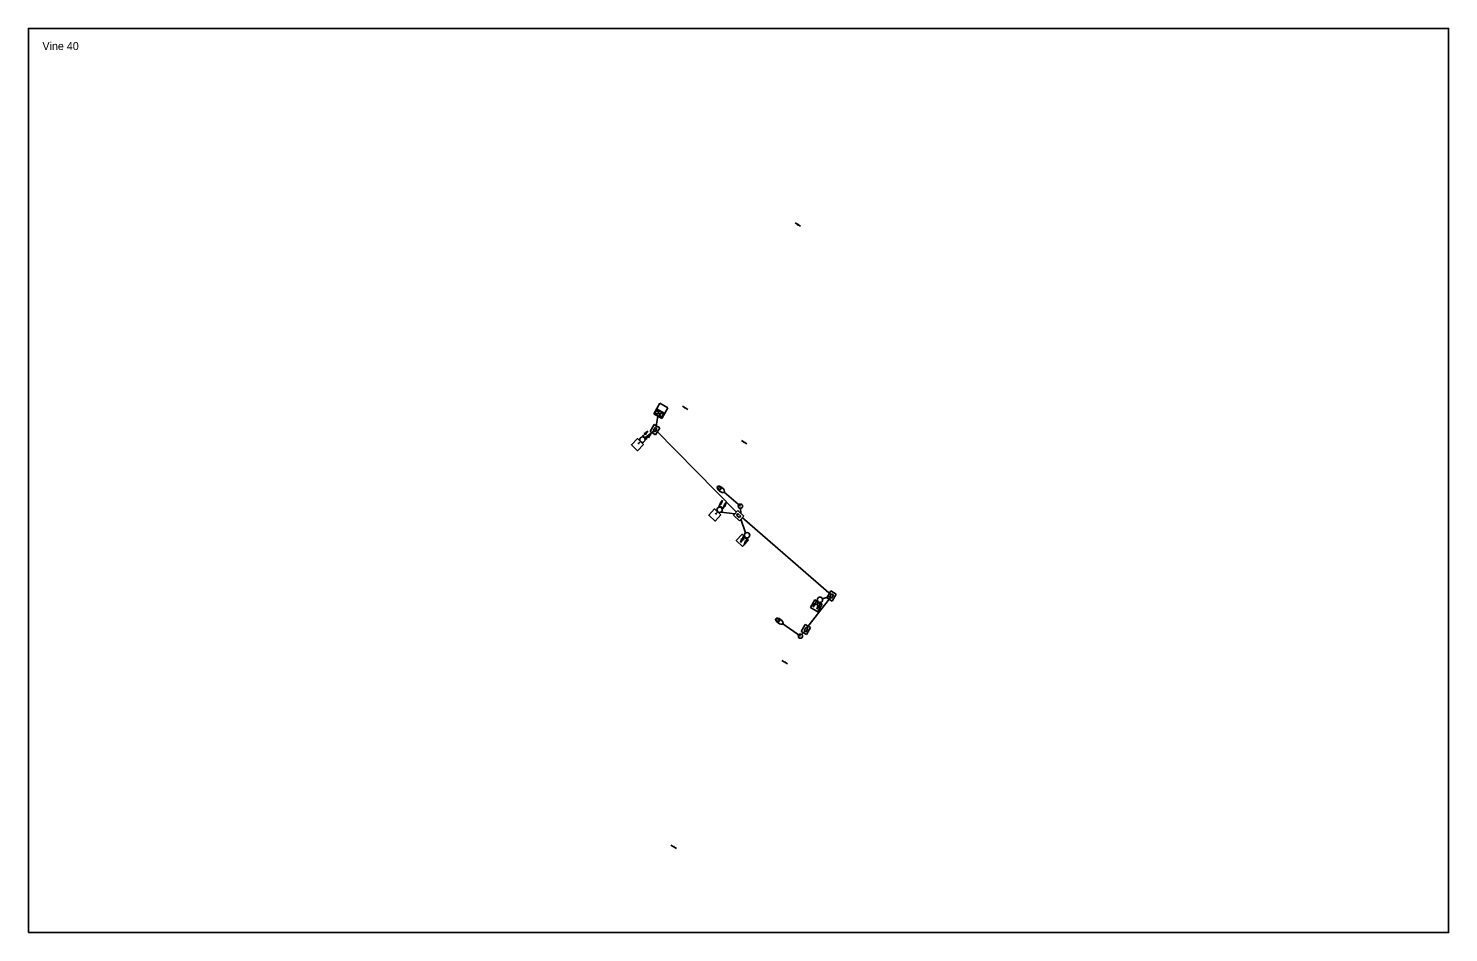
# Model space of a CAD drawing. Extents: x 995815 to 1000702, y 1981720 to 1984760.
# Drawn here: x 998107 to 998767, y 1984340 to 1984760 of the extents above; entities that cross this region are included whole.
import ezdxf

# ---------------------------------------------------------------- set-up
doc = ezdxf.new("R2010")
doc.units = 0
for name, color, linetype in [('DSN_Drain_Alignment_ArDOT_BMCD_Rt', 7, 'Continuous'), ('DSN_DRAIN_Analytics_ArDOT_BMCD_Rt', 7, 'Continuous'), ('DSN_DRFT_Common-Annotations', 7, 'Continuous'), ('DSN_DRFT_Const-No-Plot', 7, 'Continuous'), ('DSN_DRFT_Guideline-No-Plot', 7, 'Continuous'), ('DSN_DRFT_Junk-No-Plot', 7, 'Continuous'), ('DSN_RDWY_Alignment', 7, 'Continuous'), ('DSN_ROW_Point-Name-Annotation', 7, 'Continuous')]:
    doc.layers.add(name, color=color, linetype=linetype)

msp = doc.modelspace()

# ---------------------------------------------------------------- linework, layer by layer
at = {"layer": 'DSN_Drain_Alignment_ArDOT_BMCD_Rt'}
for centre in [(998437.57, 1984538.23), (998465.44, 1984477.85)]:
    msp.add_circle(centre, 1, dxfattribs=at)
at = {"layer": 'DSN_DRAIN_Analytics_ArDOT_BMCD_Rt'}
for points in [[(998392.57, 1984566.84), (998389.78, 1984563.98), (998386.92, 1984566.78), (998389.71, 1984569.63)], [(998428.5, 1984534.28), (998425.8, 1984531.33), (998422.85, 1984534.04), (998425.56, 1984536.99)], [(998441.27, 1984522.46), (998438.55, 1984519.53), (998435.61, 1984522.25), (998438.34, 1984525.18)], [(998475.61, 1984492.66), (998473.61, 1984489.19), (998470.15, 1984491.2), (998472.15, 1984494.66)]]:
    msp.add_lwpolyline(points, close=True, dxfattribs=at)
at = {"layer": 'DSN_DRFT_Common-Annotations'}
for p, q in [((998397.52, 1984576.12), (998395.62, 1984572.89)), ((998400.04, 1984574.65), (998397.52, 1984576.12)), ((998391.14, 1984568.24), (998390.22, 1984567.29)), ((998395.62, 1984572.89), (998398.15, 1984571.41)), ((998396.99, 1984573.25), (998397.87, 1984574.76)), ((998397.87, 1984574.76), (998396.99, 1984573.25)), ((998397.79, 1984572.78), (998396.99, 1984573.25)), ((998396.99, 1984573.25), (998397.79, 1984572.78)), ((998397.79, 1984572.78), (998398.67, 1984574.29)), ((998397.79, 1984572.78), (998398.67, 1984574.29)), ((998398.67, 1984574.29), (998397.87, 1984574.76)), ((998398.67, 1984574.29), (998397.87, 1984574.76)), ((998398.15, 1984571.41), (998400.04, 1984574.65)), ((998389.91, 1984567.6), (998390.53, 1984566.99)), ((998427.03, 1984535.63), (998426.14, 1984534.66)), ((998436.34, 1984536.18), (998434.35, 1984534.03)), ((998439.09, 1984533.63), (998436.34, 1984536.18)), ((998425.82, 1984534.96), (998426.46, 1984534.37)), ((998434.35, 1984534.03), (998437.1, 1984531.49)), ((998435.77, 1984534.09), (998436.39, 1984534.76)), ((998436.39, 1984534.76), (998435.77, 1984534.09)), ((998435.77, 1984534.09), (998437.05, 1984532.9)), ((998435.77, 1984534.09), (998437.05, 1984532.9)), ((998436.39, 1984534.76), (998437.68, 1984533.58)), ((998437.68, 1984533.58), (998436.39, 1984534.76)), ((998437.05, 1984532.9), (998437.68, 1984533.58)), ((998437.05, 1984532.9), (998437.68, 1984533.58)), ((998437.1, 1984531.49), (998439.09, 1984533.63)), ((998438.59, 1984523.15), (998439.23, 1984522.55)), ((998439.8, 1984523.82), (998438.91, 1984522.85)), ((998479.6, 1984498.88), (998477.72, 1984495.63)), ((998477.72, 1984495.63), (998480.24, 1984494.17)), ((998479.08, 1984496), (998479.96, 1984497.51)), ((998479.96, 1984497.51), (998479.08, 1984496)), ((998479.88, 1984495.53), (998479.08, 1984496)), ((998479.08, 1984496), (998479.88, 1984495.53)), ((998482.13, 1984497.41), (998479.6, 1984498.88)), ((998479.88, 1984495.53), (998480.76, 1984497.05)), ((998479.88, 1984495.53), (998480.76, 1984497.05)), ((998480.76, 1984497.05), (998479.96, 1984497.51)), ((998480.76, 1984497.05), (998479.96, 1984497.51)), ((998480.24, 1984494.17), (998482.13, 1984497.41)), ((998472.85, 1984492.73), (998473.6, 1984492.3)), ((998473.88, 1984493.66), (998473.22, 1984492.52)), ((998467.66, 1984483.28), (998465.8, 1984480.02)), ((998470.19, 1984481.83), (998467.66, 1984483.28)), ((998465.8, 1984480.02), (998468.33, 1984478.57)), ((998467.16, 1984480.39), (998468.03, 1984481.91)), ((998468.03, 1984481.91), (998467.16, 1984480.39)), ((998467.96, 1984479.93), (998467.16, 1984480.39)), ((998467.16, 1984480.39), (998467.96, 1984479.93)), ((998467.96, 1984479.93), (998468.83, 1984481.45)), ((998467.96, 1984479.93), (998468.83, 1984481.45)), ((998468.83, 1984481.45), (998468.03, 1984481.91)), ((998468.83, 1984481.45), (998468.03, 1984481.91)), ((998468.33, 1984478.57), (998470.19, 1984481.83))]:
    msp.add_line(p, q, dxfattribs=at)
at = {"layer": 'DSN_DRFT_Const-No-Plot'}
for p, q in [((998400.11, 1984586.07), (998397.3, 1984581.06)), ((998398.77, 1984583), (998397.75, 1984581.19)), ((998402.42, 1984581.33), (998398.64, 1984583.45)), ((998401.97, 1984581.2), (998398.77, 1984583)), ((998400.93, 1984579.4), (998398.77, 1984583)), ((998403.89, 1984583.95), (998400.11, 1984586.07)), ((998403.89, 1984583.95), (998401.08, 1984578.94)), ((998401.08, 1984578.94), (998397.3, 1984581.06)), ((998397.75, 1984581.19), (998401.97, 1984581.2)), ((998400.95, 1984579.39), (998397.75, 1984581.19)), ((998401.97, 1984581.2), (998400.95, 1984579.39))]:
    msp.add_line(p, q, dxfattribs=at)
at = {"layer": 'DSN_DRFT_Guideline-No-Plot'}
for p, q in [((998437.57, 1984538.23), (998429.97, 1984544.72)), ((998465.44, 1984477.85), (998457.29, 1984483.64))]:
    msp.add_line(p, q, dxfattribs=at)
for centre, major_axis in [((998428.45, 1984546.02), (-1.52, 1.3)), ((998427.69, 1984546.67), (0.76, -0.649)), ((998455.66, 1984484.8), (-1.63, 1.16)), ((998454.85, 1984485.38), (0.815, -0.579))]:
    msp.add_ellipse(centre, major_axis=major_axis, ratio=0.5, dxfattribs=at)
at = {"layer": 'DSN_DRFT_Junk-No-Plot'}
msp.add_lwpolyline([(998106.67, 1984340.15), (998766.67, 1984340.15), (998766.67, 1984760.15), (998106.67, 1984760.15)], close=True, dxfattribs=at)
at = {"layer": 'DSN_RDWY_Alignment'}
for p, q in [((998399.19, 1984580), (998398.27, 1984574.52)), ((998397.39, 1984573.01), (998393.03, 1984569.86)), ((998398.23, 1984573.54), (998435.68, 1984535.46)), ((998434.99, 1984534.73), (998428.58, 1984535.51)), ((998437.71, 1984534.9), (998437.61, 1984537.23)), ((998437.77, 1984532.2), (998439.96, 1984525.77)), ((998438.43, 1984532.92), (998479.67, 1984497.01)), ((998479.48, 1984495.77), (998468.43, 1984481.68)), ((998479.38, 1984496.5), (998475.69, 1984495.16)), ((998467.56, 1984480.16), (998466.12, 1984478.59))]:
    msp.add_line(p, q, dxfattribs=at)
at = {"layer": 'DSN_ROW_Point-Name-Annotation'}
for p, q in [((998465.5, 1984668.31), (998462.94, 1984669.88)), ((998463.98, 1984668.95), (998464.11, 1984669.16)), ((998463.98, 1984668.95), (998464.2, 1984668.81)), ((998464.33, 1984669.03), (998464.11, 1984669.16)), ((998464.33, 1984669.03), (998464.2, 1984668.81)), ((998413.2, 1984583.08), (998410.64, 1984584.64)), ((998411.68, 1984583.71), (998411.81, 1984583.92)), ((998411.68, 1984583.71), (998411.9, 1984583.58)), ((998412.03, 1984583.79), (998411.81, 1984583.92)), ((998412.03, 1984583.79), (998411.9, 1984583.58)), ((998394.14, 1984569.15), (998392, 1984571.24)), ((998392.36, 1984570.89), (998394.47, 1984573.05)), ((998392.9, 1984570.02), (998393.07, 1984570.2)), ((998393.79, 1984569.49), (998395.9, 1984571.65)), ((998440.61, 1984567.15), (998438.05, 1984568.71)), ((998439.1, 1984567.78), (998439.23, 1984568)), ((998439.1, 1984567.78), (998439.31, 1984567.65)), ((998439.44, 1984567.86), (998439.23, 1984568)), ((998439.44, 1984567.86), (998439.31, 1984567.65)), ((998429.93, 1984537.11), (998427.32, 1984538.59)), ((998427.76, 1984538.34), (998429.25, 1984540.97)), ((998428.5, 1984537.63), (998428.63, 1984537.85)), ((998429.5, 1984537.36), (998430.99, 1984539.98)), ((998439.04, 1984523.93), (998437.54, 1984521.31)), ((998438.6, 1984524.18), (998441.21, 1984522.69)), ((998440.77, 1984522.94), (998439.28, 1984520.32)), ((998440.03, 1984523.65), (998439.91, 1984523.43)), ((998472.89, 1984493.94), (998471.38, 1984491.32)), ((998472.46, 1984494.19), (998475.06, 1984492.69)), ((998474.62, 1984492.94), (998473.12, 1984490.33)), ((998473.88, 1984493.66), (998473.76, 1984493.44)), ((998456.82, 1984466.52), (998459.39, 1984464.98)), ((998458, 1984465.81), (998458.13, 1984466.03)), ((998458, 1984465.81), (998458.21, 1984465.68)), ((998458.34, 1984465.9), (998458.13, 1984466.03)), ((998458.34, 1984465.9), (998458.21, 1984465.68)), ((998405.29, 1984380.82), (998407.86, 1984379.27)), ((998406.47, 1984380.11), (998406.6, 1984380.33)), ((998406.47, 1984380.11), (998406.68, 1984379.98)), ((998406.81, 1984380.2), (998406.6, 1984380.33)), ((998406.81, 1984380.2), (998406.68, 1984379.98))]:
    msp.add_line(p, q, dxfattribs=at)
for centre in [(998392.02, 1984569.13), (998427.88, 1984536.55), (998440.65, 1984524.73), (998474.51, 1984494.74)]:
    msp.add_circle(centre, 1.25, dxfattribs=at)
for centre, radius, start, end in [((998385.6, 1984584.82), 14.74, 299.2828, 307.02091), ((998392.63, 1984571.17), 0.814, 13.78191, 77.47655), ((998406.43, 1984564.44), 14.74, 144.23755, 151.97566), ((998387.03, 1984583.42), 14.74, 299.2828, 307.02091), ((998394.06, 1984569.77), 0.814, 13.78191, 77.47655), ((998407.86, 1984563.04), 14.74, 144.23755, 151.97566), ((998417.66, 1984550.07), 14.74, 314.12207, 321.86019), ((998427.95, 1984538.68), 0.814, 28.62118, 92.31582), ((998443.01, 1984535.71), 14.74, 159.07682, 166.81493), ((998419.4, 1984549.08), 14.74, 314.12207, 321.86018), ((998429.69, 1984537.69), 0.814, 28.62118, 92.31582), ((998444.75, 1984534.72), 14.74, 159.07682, 166.81493), ((998423.79, 1984526.61), 14.74, 338.90438, 346.64249), ((998449.1, 1984512.17), 14.74, 133.94963, 141.68774), ((998438.84, 1984523.59), 0.814, 208.44874, 272.14338), ((998425.53, 1984525.62), 14.74, 338.90438, 346.64249), ((998440.58, 1984522.6), 0.814, 208.44874, 272.14338), ((998450.84, 1984511.18), 14.74, 133.94963, 141.68774), ((998457.65, 1984496.68), 14.74, 338.68246, 346.42058), ((998482.91, 1984482.14), 14.74, 133.72772, 141.46583), ((998472.7, 1984493.61), 0.814, 208.22683, 271.92146), ((998459.39, 1984495.68), 14.74, 338.68246, 346.42058), ((998484.64, 1984481.15), 14.74, 133.72772, 141.46583), ((998474.43, 1984492.61), 0.814, 208.22683, 271.92146)]:
    msp.add_arc(centre, radius, start, end, dxfattribs=at)

# ---------------------------------------------------------------- texts
at = {"layer": 'DSN_DRFT_Junk-No-Plot'}
msp.add_text('Vine 40', height=3.72, rotation=359.97484, dxfattribs=at).set_placement((998113.19, 1984750.11))

doc.saveas('drawing.dxf')
